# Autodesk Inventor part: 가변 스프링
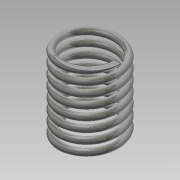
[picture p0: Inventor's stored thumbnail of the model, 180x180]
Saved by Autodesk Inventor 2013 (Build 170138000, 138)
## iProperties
Created: 2015-01
Part Number: 가변 스프링
Material: 강철, 탄소
Document SubType Name: Modeling
Designer: hanacad7
Density: 7.87 g/cm^3
Mass: 80.13 g
Surface Area: 103.216 cm^2
Volume: 10.1817 cm^3
Author: hanacad7
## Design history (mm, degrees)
sketch "스케치1"
  geometry: L1 (0, 0)-(17.5, 0); L2 (17.5, 0)-(17.5, 48.5); L3 (17.5, 48.5)-(0, 48.5); L4 (0, 48.5)-(0, 0); C1 r 2 at (17.5, 0)
  constraints: 8 end point, 2 parallel, 1 centre point, 1 coincident, 1 horizontal, 1 perpendicular
  dimensions: "d0" = 4 diameter of C1; "d2" = 35 diameter of L2 L4; "d3" = 48.5 distance between parallel lines of L1 L3 (derived)
feature "코일1" sketch "스케치1" pitch "d4" = 10; turns "d6" = 7.5; dims "d5" = 48.5 (= d3), "d7" = 0, angle "d8" = 90 deg, angle "d9" = 90 deg, "d10" = 0, "d11" = 0
sketch "스케치2"
  geometry: L1 (-19.5, 0)-(-15.5, 0) reference; 1 further point
  constraints: 1 horizontal alignment
extrude "돌출1" cut sketch "스케치2" stored distance "d12" = 10; taper "d13" = 0 deg
node "작업 평면1"
sketch "스케치3"
  geometry: L1 (15.5, 0)-(19.5, 0) reference; 1 further point
  constraints: 1 horizontal alignment
extrude "돌출2" cut sketch "스케치3" stored distance "d14" = 10; taper "d15" = 0 deg
node "솔리드1"
node "절단 모서리 투영1"
node "절단 모서리 투영2"
